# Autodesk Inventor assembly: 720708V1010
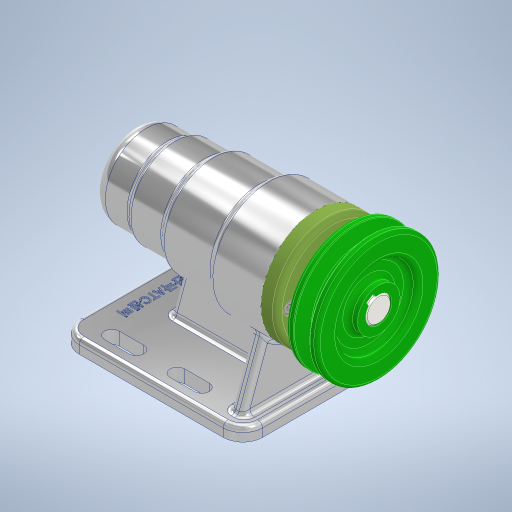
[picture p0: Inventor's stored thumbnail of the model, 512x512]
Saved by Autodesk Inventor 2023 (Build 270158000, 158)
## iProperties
Created: 2022-07
Part Number: 720708V1010
Document SubType Name: Assembly
Designer: owner
Author: owner
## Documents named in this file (12)
- C:\Users\owner\Desktop\720708V1010\720708V1010.iam
- C:\Users\owner\Desktop\720708V1010\본체.ipt
- C:\Users\owner\Desktop\720708V1010\V벨트풀리.ipt
- C:\Users\owner\Desktop\720708V1010\멈춤나사 M3.ipt
- C:\Users\owner\Desktop\720708V1010\베어링 6004.ipt
- C:\Users\owner\Desktop\720708V1010\베어링 51202.ipt
- C:\Users\owner\Desktop\720708V1010\볼트 M4.ipt
- C:\Users\owner\Desktop\720708V1010\어댑터슬리브.ipt
- C:\Users\owner\Desktop\720708V1010\오일 실 20x35x7.ipt
- C:\Users\owner\Desktop\720708V1010\축.ipt
- C:\Users\owner\Desktop\720708V1010\커버.ipt
- C:\Users\owner\Desktop\720708V1010\키 5x5.ipt
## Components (1 placed, 1 different names)
1. V벨트풀리:1
